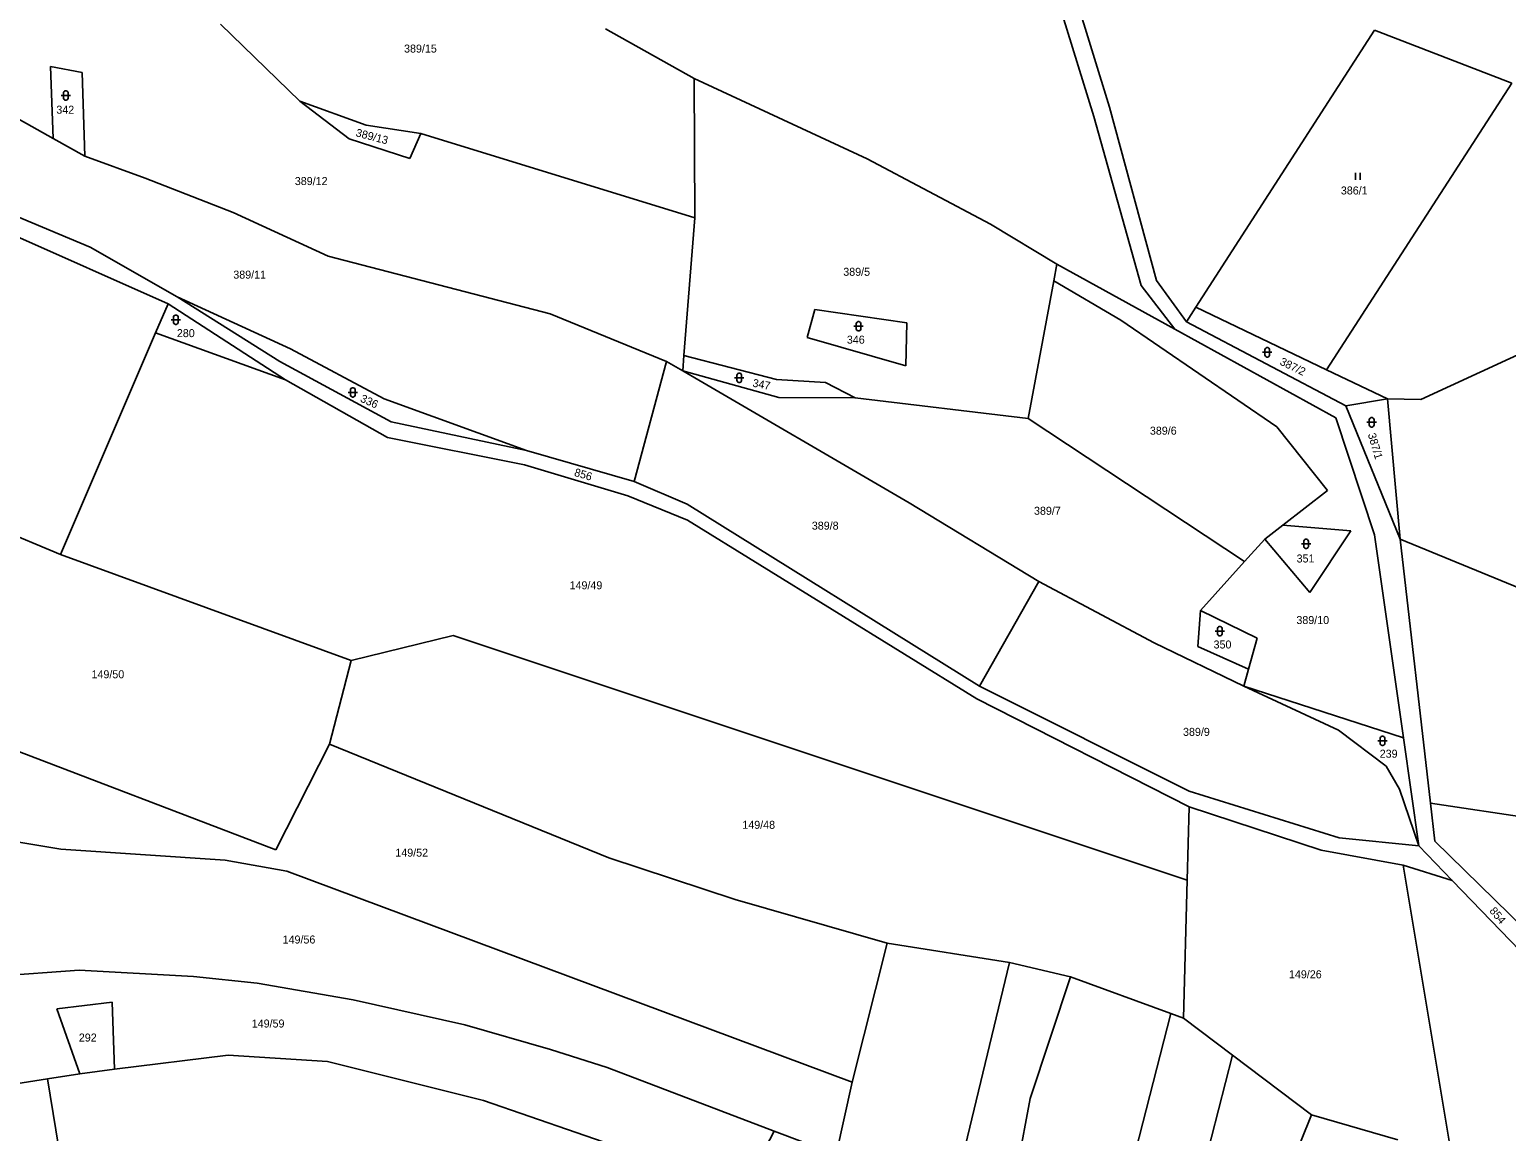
# Model space of a CAD drawing. Extents: x -791032 to -787751, y -1106872 to -1104403.
# Drawn here: x -790161.3 to -789847.4, y -1104928.1 to -1104694 of the extents above; entities that cross this region are included whole.
import ezdxf

# ---------------------------------------------------------------- set-up
doc = ezdxf.new("R2010")
doc.units = 0
for name, color, linetype in [('Vrstva 1', 7, 'Continuous'), ('Vrstva 14', 7, 'Continuous'), ('Vrstva 23', 7, 'Continuous')]:
    doc.layers.add(name, color=color, linetype=linetype)

msp = doc.modelspace()

# ---------------------------------------------------------------- linework, layer by layer
at = {"layer": 'Vrstva 1'}
for p, q in [((-789935.06, -1104712.42), (-789945, -1104680.47)), ((-789931.79, -1104710.42), (-789940.62, -1104681.61)), ((-790120.69, -1104692.79), (-790103.79, -1104709.16)), ((-790020.02, -1104704.39), (-790038.87, -1104693.81)), ((-789913.43, -1104752.93), (-789875.47, -1104694.1)), ((-789875.47, -1104694.1), (-789846.27, -1104705.37)), ((-790150.06, -1104703.05), (-790156.82, -1104701.81)), ((-790156.82, -1104701.81), (-790156.22, -1104717.14)), ((-790149.54, -1104720.88), (-790150.06, -1104703.05)), ((-790178.5, -1104704.66), (-790156.22, -1104717.14)), ((-789983.24, -1104721.45), (-790020.02, -1104704.39)), ((-790019.87, -1104733.94), (-790020.02, -1104704.39)), ((-789885.63, -1104766.23), (-789846.27, -1104705.37)), ((-790093.31, -1104717.2), (-790103.79, -1104709.16)), ((-790103.79, -1104709.16), (-790089.69, -1104714.26)), ((-789925.04, -1104748.32), (-789935.06, -1104712.42)), ((-789921.75, -1104747.3), (-789931.79, -1104710.42)), ((-790089.69, -1104714.26), (-790078.09, -1104716.06)), ((-790156.22, -1104717.14), (-790149.54, -1104720.88)), ((-790080.45, -1104721.37), (-790093.31, -1104717.2)), ((-790078.09, -1104716.06), (-790080.45, -1104721.37)), ((-790078.09, -1104716.06), (-790019.87, -1104733.94)), ((-790149.54, -1104720.88), (-790136.71, -1104725.54)), ((-789957.04, -1104735.32), (-789983.24, -1104721.45)), ((-790136.71, -1104725.54), (-790117.99, -1104732.86)), ((-790165.06, -1104733.18), (-790148.37, -1104740.22)), ((-790117.99, -1104732.86), (-790097.8, -1104742.08)), ((-790022.2, -1104763.2), (-790019.87, -1104733.94)), ((-790165.88, -1104737.09), (-790131.83, -1104752.23)), ((-789942.93, -1104743.78), (-789957.04, -1104735.32)), ((-790148.37, -1104740.22), (-790129.86, -1104750.77)), ((-790097.8, -1104742.08), (-790050.62, -1104754.36)), ((-789943.6, -1104747.35), (-789942.93, -1104743.78)), ((-789917.88, -1104757.59), (-789942.93, -1104743.78)), ((-789949.07, -1104776.58), (-789943.6, -1104747.35)), ((-789929.36, -1104755.71), (-789943.6, -1104747.35)), ((-789915.43, -1104756.03), (-789921.75, -1104747.3)), ((-789917.88, -1104757.59), (-789925.04, -1104748.32)), ((-790131.83, -1104752.23), (-790134.48, -1104758.39)), ((-790131.83, -1104752.23), (-790106.89, -1104768.39)), ((-790129.86, -1104750.77), (-790105.82, -1104761.77)), ((-790108.04, -1104764.52), (-790129.86, -1104750.77)), ((-789994.4, -1104753.41), (-789995.99, -1104759.41)), ((-789974.83, -1104756.24), (-789994.4, -1104753.41)), ((-789915.43, -1104756.03), (-789913.43, -1104752.93)), ((-789913.43, -1104752.93), (-789885.63, -1104766.23)), ((-790050.62, -1104754.36), (-790025.92, -1104764.46)), ((-789975.07, -1104765.41), (-789974.83, -1104756.24)), ((-789896.18, -1104778.37), (-789929.36, -1104755.71)), ((-789881.54, -1104773.92), (-789915.43, -1104756.03)), ((-790154.67, -1104805.5), (-790134.48, -1104758.39)), ((-790134.48, -1104758.39), (-790106.89, -1104768.39)), ((-789995.99, -1104759.41), (-789975.07, -1104765.41)), ((-789883.68, -1104776.44), (-789917.88, -1104757.59)), ((-789865.59, -1104772.57), (-789836.96, -1104759.34)), ((-790085.9, -1104772.44), (-790105.82, -1104761.77)), ((-790108.04, -1104764.52), (-790084.42, -1104777.3)), ((-790032.77, -1104789.96), (-790025.92, -1104764.46)), ((-790025.92, -1104764.46), (-790022.46, -1104766.47)), ((-790022.46, -1104766.47), (-790022.2, -1104763.2)), ((-790002.56, -1104768.35), (-790022.2, -1104763.2)), ((-789885.63, -1104766.23), (-789872.66, -1104772.43)), ((-790106.89, -1104768.39), (-790085.21, -1104780.61)), ((-789974.32, -1104794.49), (-790022.46, -1104766.47)), ((-790022.46, -1104766.47), (-790002, -1104772.13)), ((-789992.09, -1104768.92), (-790002.56, -1104768.35)), ((-789985.84, -1104772.2), (-789992.09, -1104768.92)), ((-790055.63, -1104783.4), (-790085.9, -1104772.44)), ((-790002, -1104772.13), (-789985.84, -1104772.2)), ((-789985.84, -1104772.2), (-789949.07, -1104776.58)), ((-789881.54, -1104773.92), (-789872.66, -1104772.43)), ((-789872.66, -1104772.43), (-789869.98, -1104802.22)), ((-789872.66, -1104772.43), (-789865.59, -1104772.57)), ((-789869.98, -1104802.22), (-789881.54, -1104773.92)), ((-790084.42, -1104777.3), (-790055.63, -1104783.4)), ((-789903.06, -1104806.99), (-789949.07, -1104776.58)), ((-789885.44, -1104791.9), (-789896.18, -1104778.37)), ((-789875.45, -1104801.33), (-789883.68, -1104776.44)), ((-790085.21, -1104780.61), (-790056.1, -1104786.47)), ((-790055.63, -1104783.4), (-790032.77, -1104789.96)), ((-790056.1, -1104786.47), (-790034.12, -1104793.03)), ((-790032.77, -1104789.96), (-790021.48, -1104794.8)), ((-790034.12, -1104793.03), (-790021.42, -1104798.2)), ((-789946.81, -1104811.25), (-789974.32, -1104794.49)), ((-789894.94, -1104799.25), (-789885.44, -1104791.9)), ((-790154.67, -1104805.5), (-790180.14, -1104794.87)), ((-790021.48, -1104794.8), (-789959.36, -1104833.45)), ((-790021.42, -1104798.2), (-789959.97, -1104836.18)), ((-789898.78, -1104802.22), (-789894.94, -1104799.25)), ((-789880.5, -1104800.45), (-789894.94, -1104799.25)), ((-789889.2, -1104813.56), (-789880.5, -1104800.45)), ((-789903.06, -1104806.99), (-789898.78, -1104802.22)), ((-789898.78, -1104802.22), (-789889.2, -1104813.56)), ((-789869.31, -1104844.49), (-789875.45, -1104801.33)), ((-789869.98, -1104802.22), (-789863.58, -1104858.36)), ((-789869.98, -1104802.22), (-789841.85, -1104813.76)), ((-790092.91, -1104828.03), (-790154.67, -1104805.5)), ((-789912.41, -1104817.41), (-789903.06, -1104806.99)), ((-789959.36, -1104833.45), (-789946.81, -1104811.25)), ((-789922.26, -1104824.25), (-789946.81, -1104811.25)), ((-789912.41, -1104817.41), (-789913, -1104825.06)), ((-789900.42, -1104823.29), (-789912.41, -1104817.41)), ((-790092.91, -1104828.03), (-790071.21, -1104822.72)), ((-789915.26, -1104874.72), (-790071.21, -1104822.72)), ((-789903.23, -1104833.46), (-789922.26, -1104824.25)), ((-789913, -1104825.06), (-789902.23, -1104829.86)), ((-789902.23, -1104829.86), (-789900.42, -1104823.29)), ((-790097.5, -1104845.81), (-790092.91, -1104828.03)), ((-789902.23, -1104829.86), (-789903.23, -1104833.46)), ((-789959.36, -1104833.45), (-789914.84, -1104855.78)), ((-789903.23, -1104833.46), (-789869.31, -1104844.49)), ((-789883.07, -1104842.8), (-789903.23, -1104833.46)), ((-789959.97, -1104836.18), (-789914.86, -1104859.09)), ((-790173.93, -1104843.41), (-790108.92, -1104868.24)), ((-789872.96, -1104850.47), (-789883.07, -1104842.8)), ((-789866.06, -1104867.39), (-789869.31, -1104844.49)), ((-790108.92, -1104868.24), (-790097.5, -1104845.81)), ((-790038.16, -1104869.95), (-790097.5, -1104845.81)), ((-789870.14, -1104855.38), (-789872.96, -1104850.47)), ((-789914.84, -1104855.78), (-789882.99, -1104865.68)), ((-789866.06, -1104867.39), (-789870.14, -1104855.38)), ((-789915.26, -1104874.72), (-789914.86, -1104859.09)), ((-789914.86, -1104859.09), (-789886.79, -1104868.31)), ((-789863.58, -1104858.36), (-789862.66, -1104866.44)), ((-789863.58, -1104858.36), (-789841.81, -1104861.62)), ((-790197.32, -1104860.92), (-790154.61, -1104868.11)), ((-789882.99, -1104865.68), (-789866.06, -1104867.39)), ((-789862.66, -1104866.44), (-789829.64, -1104898.65)), ((-790154.61, -1104868.11), (-790119.69, -1104870.42)), ((-789886.79, -1104868.31), (-789869.36, -1104871.5)), ((-789866.06, -1104867.39), (-789858.93, -1104874.79)), ((-790119.69, -1104870.42), (-790106.55, -1104872.77)), ((-789986.43, -1104917.64), (-790106.55, -1104872.77)), ((-790011.28, -1104878.8), (-790038.16, -1104869.95)), ((-789859.1, -1104933.15), (-789869.36, -1104871.5)), ((-789869.36, -1104871.5), (-789858.93, -1104874.79)), ((-789916.02, -1104903.99), (-789915.26, -1104874.72)), ((-789858.93, -1104874.79), (-789834.34, -1104900.29)), ((-789979.02, -1104888.09), (-790011.28, -1104878.8)), ((-789979.02, -1104888.09), (-789986.43, -1104917.64)), ((-789953.01, -1104892.16), (-789979.02, -1104888.09)), ((-790206.04, -1104897.85), (-790150.74, -1104893.79)), ((-790150.74, -1104893.79), (-790126.4, -1104895.16)), ((-789965.97, -1104946.09), (-789953.01, -1104892.16)), ((-789940.07, -1104895.25), (-789953.01, -1104892.16)), ((-790126.4, -1104895.16), (-790112.89, -1104896.62)), ((-790112.89, -1104896.62), (-790092.45, -1104900.15)), ((-789948.6, -1104921.06), (-789940.07, -1104895.25)), ((-789918.76, -1104903), (-789940.07, -1104895.25)), ((-790155.42, -1104902.06), (-790143.68, -1104900.65)), ((-790143.68, -1104900.65), (-790143.2, -1104914.84)), ((-790092.45, -1104900.15), (-790068.79, -1104905.47)), ((-790150.57, -1104915.85), (-790155.42, -1104902.06)), ((-789943.92, -1105001.5), (-789918.76, -1104903)), ((-789916.02, -1104903.99), (-789918.76, -1104903)), ((-789905.62, -1104911.87), (-789916.02, -1104903.99)), ((-790068.79, -1104905.47), (-790050.52, -1104910.65)), ((-790143.2, -1104914.84), (-790119.07, -1104911.89)), ((-790119.07, -1104911.89), (-790097.93, -1104913.2)), ((-790097.93, -1104913.2), (-790064.79, -1104921.49)), ((-790050.52, -1104910.65), (-790038.48, -1104914.52)), ((-789952.37, -1105094.05), (-789905.62, -1104911.87)), ((-789888.86, -1104924.56), (-789905.62, -1104911.87)), ((-790157.45, -1104916.94), (-790150.57, -1104915.85)), ((-790150.57, -1104915.85), (-790143.2, -1104914.84)), ((-790003.03, -1104928), (-790038.48, -1104914.52)), ((-790214.49, -1104925.91), (-790157.45, -1104916.94)), ((-790154.32, -1104936.14), (-790157.45, -1104916.94)), ((-789986.43, -1104917.64), (-789989.87, -1104933.01)), ((-790010.15, -1104940.33), (-790064.79, -1104921.49)), ((-789955.11, -1104955.89), (-789948.6, -1104921.06)), ((-789899.07, -1104949.75), (-789888.86, -1104924.56)), ((-789870.5, -1104929.86), (-789888.86, -1104924.56)), ((-790009.5, -1104940.55), (-790003.03, -1104928)), ((-789989.87, -1104933.01), (-790003.03, -1104928))]:
    msp.add_line(p, q, dxfattribs=at)
at = {"layer": 'Vrstva 23'}
for p, q in [((-790154.55, -1104707.96), (-790152.55, -1104707.96)), ((-790154.05, -1104707.36), (-790153.95, -1104707.16)), ((-790154.05, -1104708.56), (-790154.05, -1104707.36)), ((-790153.95, -1104708.76), (-790154.05, -1104708.56)), ((-790153.95, -1104707.16), (-790153.85, -1104707.06)), ((-790153.85, -1104708.86), (-790153.95, -1104708.76)), ((-790153.85, -1104707.06), (-790153.65, -1104706.96)), ((-790153.65, -1104708.96), (-790153.85, -1104708.86)), ((-790153.65, -1104706.96), (-790153.45, -1104706.96)), ((-790153.45, -1104708.96), (-790153.65, -1104708.96)), ((-790153.45, -1104706.96), (-790153.25, -1104707.06)), ((-790153.25, -1104708.86), (-790153.45, -1104708.96)), ((-790153.25, -1104707.06), (-790153.15, -1104707.16)), ((-790153.15, -1104708.76), (-790153.25, -1104708.86)), ((-790153.15, -1104707.16), (-790153.05, -1104707.36)), ((-790153.05, -1104708.56), (-790153.15, -1104708.76)), ((-790153.05, -1104707.36), (-790153.05, -1104708.56)), ((-789879.5, -1104725.91), (-789879.5, -1104724.41)), ((-789878.5, -1104724.41), (-789878.5, -1104725.91)), ((-790131.16, -1104755.62), (-790129.16, -1104755.62)), ((-790130.66, -1104755.02), (-790130.56, -1104754.82)), ((-790130.66, -1104756.22), (-790130.66, -1104755.02)), ((-790130.56, -1104756.42), (-790130.66, -1104756.22)), ((-790130.56, -1104754.82), (-790130.46, -1104754.72)), ((-790130.46, -1104756.52), (-790130.56, -1104756.42)), ((-790130.46, -1104754.72), (-790130.26, -1104754.62)), ((-790130.26, -1104756.62), (-790130.46, -1104756.52)), ((-790130.26, -1104754.62), (-790130.06, -1104754.62)), ((-790130.06, -1104756.62), (-790130.26, -1104756.62)), ((-790130.06, -1104754.62), (-790129.86, -1104754.72)), ((-790129.86, -1104756.52), (-790130.06, -1104756.62)), ((-790129.86, -1104754.72), (-790129.76, -1104754.82)), ((-790129.76, -1104756.42), (-790129.86, -1104756.52)), ((-790129.76, -1104754.82), (-790129.66, -1104755.02)), ((-790129.66, -1104756.22), (-790129.76, -1104756.42)), ((-790129.66, -1104755.02), (-790129.66, -1104756.22)), ((-789985.59, -1104756.4), (-789985.49, -1104756.2)), ((-789985.59, -1104757.6), (-789985.59, -1104756.4)), ((-789985.49, -1104756.2), (-789985.39, -1104756.1)), ((-789985.39, -1104756.1), (-789985.19, -1104756)), ((-789985.19, -1104756), (-789984.99, -1104756)), ((-789984.99, -1104756), (-789984.79, -1104756.1)), ((-789984.79, -1104756.1), (-789984.69, -1104756.2)), ((-789984.69, -1104756.2), (-789984.59, -1104756.4)), ((-789984.59, -1104756.4), (-789984.59, -1104757.6)), ((-789986.09, -1104757), (-789984.09, -1104757)), ((-789985.49, -1104757.8), (-789985.59, -1104757.6)), ((-789985.39, -1104757.9), (-789985.49, -1104757.8)), ((-789985.19, -1104758), (-789985.39, -1104757.9)), ((-789984.99, -1104758), (-789985.19, -1104758)), ((-789984.79, -1104757.9), (-789984.99, -1104758)), ((-789984.69, -1104757.8), (-789984.79, -1104757.9)), ((-789984.59, -1104757.6), (-789984.69, -1104757.8)), ((-789899.24, -1104762.54), (-789897.24, -1104762.54)), ((-789898.74, -1104761.94), (-789898.64, -1104761.74)), ((-789898.74, -1104763.14), (-789898.74, -1104761.94)), ((-789898.64, -1104761.74), (-789898.54, -1104761.64)), ((-789898.54, -1104761.64), (-789898.34, -1104761.54)), ((-789898.34, -1104761.54), (-789898.14, -1104761.54)), ((-789898.14, -1104761.54), (-789897.94, -1104761.64)), ((-789897.94, -1104761.64), (-789897.84, -1104761.74)), ((-789897.84, -1104761.74), (-789897.74, -1104761.94)), ((-789897.74, -1104761.94), (-789897.74, -1104763.14)), ((-789898.64, -1104763.34), (-789898.74, -1104763.14)), ((-789898.54, -1104763.44), (-789898.64, -1104763.34)), ((-789898.34, -1104763.54), (-789898.54, -1104763.44)), ((-789898.14, -1104763.54), (-789898.34, -1104763.54)), ((-789897.94, -1104763.44), (-789898.14, -1104763.54)), ((-789897.84, -1104763.34), (-789897.94, -1104763.44)), ((-789897.74, -1104763.14), (-789897.84, -1104763.34)), ((-790011.44, -1104767.96), (-790009.44, -1104767.96)), ((-790010.94, -1104767.36), (-790010.84, -1104767.16)), ((-790010.94, -1104768.56), (-790010.94, -1104767.36)), ((-790010.84, -1104768.76), (-790010.94, -1104768.56)), ((-790010.84, -1104767.16), (-790010.74, -1104767.06)), ((-790010.74, -1104768.86), (-790010.84, -1104768.76)), ((-790010.74, -1104767.06), (-790010.54, -1104766.96)), ((-790010.54, -1104768.96), (-790010.74, -1104768.86)), ((-790010.54, -1104766.96), (-790010.34, -1104766.96)), ((-790010.34, -1104768.96), (-790010.54, -1104768.96)), ((-790010.34, -1104766.96), (-790010.14, -1104767.06)), ((-790010.14, -1104768.86), (-790010.34, -1104768.96)), ((-790010.14, -1104767.06), (-790010.04, -1104767.16)), ((-790010.04, -1104768.76), (-790010.14, -1104768.86)), ((-790010.04, -1104767.16), (-790009.94, -1104767.36)), ((-790009.94, -1104768.56), (-790010.04, -1104768.76)), ((-790009.94, -1104767.36), (-790009.94, -1104768.56)), ((-790093.56, -1104771.06), (-790091.56, -1104771.06)), ((-790093.06, -1104770.46), (-790092.96, -1104770.26)), ((-790093.06, -1104771.66), (-790093.06, -1104770.46)), ((-790092.96, -1104771.86), (-790093.06, -1104771.66)), ((-790092.96, -1104770.26), (-790092.86, -1104770.16)), ((-790092.86, -1104771.96), (-790092.96, -1104771.86)), ((-790092.86, -1104770.16), (-790092.66, -1104770.06)), ((-790092.66, -1104772.06), (-790092.86, -1104771.96)), ((-790092.66, -1104770.06), (-790092.46, -1104770.06)), ((-790092.46, -1104772.06), (-790092.66, -1104772.06)), ((-790092.46, -1104770.06), (-790092.26, -1104770.16)), ((-790092.26, -1104771.96), (-790092.46, -1104772.06)), ((-790092.26, -1104770.16), (-790092.16, -1104770.26)), ((-790092.16, -1104771.86), (-790092.26, -1104771.96)), ((-790092.16, -1104770.26), (-790092.06, -1104770.46)), ((-790092.06, -1104771.66), (-790092.16, -1104771.86)), ((-790092.06, -1104770.46), (-790092.06, -1104771.66)), ((-789877.06, -1104777.41), (-789875.06, -1104777.41)), ((-789876.56, -1104776.81), (-789876.46, -1104776.61)), ((-789876.56, -1104778.01), (-789876.56, -1104776.81)), ((-789876.46, -1104778.21), (-789876.56, -1104778.01)), ((-789876.46, -1104776.61), (-789876.36, -1104776.51)), ((-789876.36, -1104778.31), (-789876.46, -1104778.21)), ((-789876.36, -1104776.51), (-789876.16, -1104776.41)), ((-789876.16, -1104778.41), (-789876.36, -1104778.31)), ((-789876.16, -1104776.41), (-789875.96, -1104776.41)), ((-789875.96, -1104778.41), (-789876.16, -1104778.41)), ((-789875.96, -1104776.41), (-789875.76, -1104776.51)), ((-789875.76, -1104778.31), (-789875.96, -1104778.41)), ((-789875.76, -1104776.51), (-789875.66, -1104776.61)), ((-789875.66, -1104778.21), (-789875.76, -1104778.31)), ((-789875.66, -1104776.61), (-789875.56, -1104776.81)), ((-789875.56, -1104778.01), (-789875.66, -1104778.21)), ((-789875.56, -1104776.81), (-789875.56, -1104778.01)), ((-789890.99, -1104803.24), (-789888.99, -1104803.24)), ((-789890.49, -1104802.64), (-789890.39, -1104802.44)), ((-789890.49, -1104803.84), (-789890.49, -1104802.64)), ((-789890.39, -1104804.04), (-789890.49, -1104803.84)), ((-789890.39, -1104802.44), (-789890.29, -1104802.34)), ((-789890.29, -1104802.34), (-789890.09, -1104802.24)), ((-789890.09, -1104802.24), (-789889.89, -1104802.24)), ((-789889.89, -1104802.24), (-789889.69, -1104802.34)), ((-789889.69, -1104802.34), (-789889.59, -1104802.44)), ((-789889.59, -1104802.44), (-789889.49, -1104802.64)), ((-789889.49, -1104803.84), (-789889.59, -1104804.04)), ((-789889.49, -1104802.64), (-789889.49, -1104803.84)), ((-789890.29, -1104804.14), (-789890.39, -1104804.04)), ((-789890.09, -1104804.24), (-789890.29, -1104804.14)), ((-789889.89, -1104804.24), (-789890.09, -1104804.24)), ((-789889.69, -1104804.14), (-789889.89, -1104804.24)), ((-789889.59, -1104804.04), (-789889.69, -1104804.14)), ((-789909.33, -1104821.79), (-789907.33, -1104821.79)), ((-789908.83, -1104821.19), (-789908.73, -1104820.99)), ((-789908.83, -1104822.39), (-789908.83, -1104821.19)), ((-789908.73, -1104822.59), (-789908.83, -1104822.39)), ((-789908.73, -1104820.99), (-789908.63, -1104820.89)), ((-789908.63, -1104822.69), (-789908.73, -1104822.59)), ((-789908.63, -1104820.89), (-789908.43, -1104820.79)), ((-789908.43, -1104822.79), (-789908.63, -1104822.69)), ((-789908.43, -1104820.79), (-789908.23, -1104820.79)), ((-789908.23, -1104820.79), (-789908.03, -1104820.89)), ((-789908.03, -1104822.69), (-789908.23, -1104822.79)), ((-789908.03, -1104820.89), (-789907.93, -1104820.99)), ((-789907.93, -1104822.59), (-789908.03, -1104822.69)), ((-789907.93, -1104820.99), (-789907.83, -1104821.19)), ((-789907.83, -1104822.39), (-789907.93, -1104822.59)), ((-789907.83, -1104821.19), (-789907.83, -1104822.39)), ((-789908.23, -1104822.79), (-789908.43, -1104822.79)), ((-789874.25, -1104844.5), (-789874.15, -1104844.3)), ((-789874.25, -1104845.7), (-789874.25, -1104844.5)), ((-789874.15, -1104844.3), (-789874.05, -1104844.2)), ((-789874.05, -1104844.2), (-789873.85, -1104844.1)), ((-789873.85, -1104844.1), (-789873.65, -1104844.1)), ((-789873.65, -1104844.1), (-789873.45, -1104844.2)), ((-789873.45, -1104844.2), (-789873.35, -1104844.3)), ((-789873.35, -1104844.3), (-789873.25, -1104844.5)), ((-789873.25, -1104844.5), (-789873.25, -1104845.7)), ((-789874.75, -1104845.1), (-789872.75, -1104845.1)), ((-789874.15, -1104845.9), (-789874.25, -1104845.7)), ((-789874.05, -1104846), (-789874.15, -1104845.9)), ((-789873.85, -1104846.1), (-789874.05, -1104846)), ((-789873.65, -1104846.1), (-789873.85, -1104846.1)), ((-789873.45, -1104846), (-789873.65, -1104846.1)), ((-789873.35, -1104845.9), (-789873.45, -1104846)), ((-789873.25, -1104845.7), (-789873.35, -1104845.9))]:
    msp.add_line(p, q, dxfattribs=at)

# ---------------------------------------------------------------- texts
at = {"layer": 'Vrstva 14'}
for s, p in [('389/15', (-790081.669, -1104698.85)), ('342', (-790155.562, -1104711.84)), ('389/12', (-790104.883, -1104727)), ('386/1', (-789882.603, -1104729)), ('389/11', (-790117.956, -1104746.88)), ('389/5', (-789988.336, -1104746.28)), ('280', (-790129.946, -1104759.31)), ('346', (-789987.573, -1104760.7)), ('389/6', (-789923.18, -1104780.04)), ('389/7', (-789947.806, -1104797.06)), ('389/8', (-789995.02, -1104800.22)), ('351', (-789892.006, -1104807.2)), ('149/49', (-790046.495, -1104812.89)), ('389/10', (-789892.052, -1104820.28)), ('350', (-789909.652, -1104825.47)), ('149/50', (-790148.084, -1104831.8)), ('389/9', (-789916.14, -1104844.04)), ('239', (-789874.347, -1104848.68)), ('149/48', (-790009.785, -1104863.79)), ('149/52', (-790083.525, -1104869.7)), ('149/56', (-790107.475, -1104888.16)), ('149/26', (-789893.629, -1104895.55)), ('149/59', (-790114.035, -1104906.01)), ('292', (-790150.776, -1104908.99))]:
    msp.add_text(s, height=1.7, dxfattribs=at).set_placement(p)
for s, rotation, p in [('389/13', 345.39552, (-790092.053, -1104716.615)), ('387/2', 333.88551, (-789895.736, -1104765.067)), ('347', 348.94071, (-790007.727, -1104769.818)), ('336', 335.5056, (-790091.115, -1104772.952)), ('387/1', 286.34112, (-789876.888, -1104779.963)), ('856', 343.49562, (-790045.641, -1104788.765)), ('854', 310.09194, (-789851.132, -1104881.279))]:
    msp.add_text(s, height=1.7, rotation=rotation, dxfattribs=at).set_placement(p)

doc.saveas('drawing.dxf')
